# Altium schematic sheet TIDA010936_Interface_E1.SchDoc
size 431 x 279 mm; Date: Not shown in title block; ApprovedBy: Not shown in title block; CheckedBy: Not shown in title block; Author: Not shown in title block; CompanyName: Not shown in title block; Engineer: Not shown in title block; Organization: Not shown in title block; Address1: Not shown in title block; Address2: Not shown in title block; Address3: Not shown in title block; Address4: Not shown in title block; DocumentNumber: 2; Revision: Use project parameter SCH_Rev; SheetNumber: 3; SheetTotal: 5; PageSetup: Record=PageOptions¦CenterHorizontal=True¦CenterVertical=True¦PrintScale=1.00¦XCorrection=1.00¦YCorrection=1.00¦PrintKind=0¦BorderSize=5000000¦LeftOffset=0¦BottomOffset=0¦Orientation=2¦PaperLength=1000¦PaperWidth=1000¦Scale=100¦PaperSource=15¦PrintQuality=600¦MediaType=1¦DitherType=10¦PaperKind=Letter¦PrintScaleMode=1
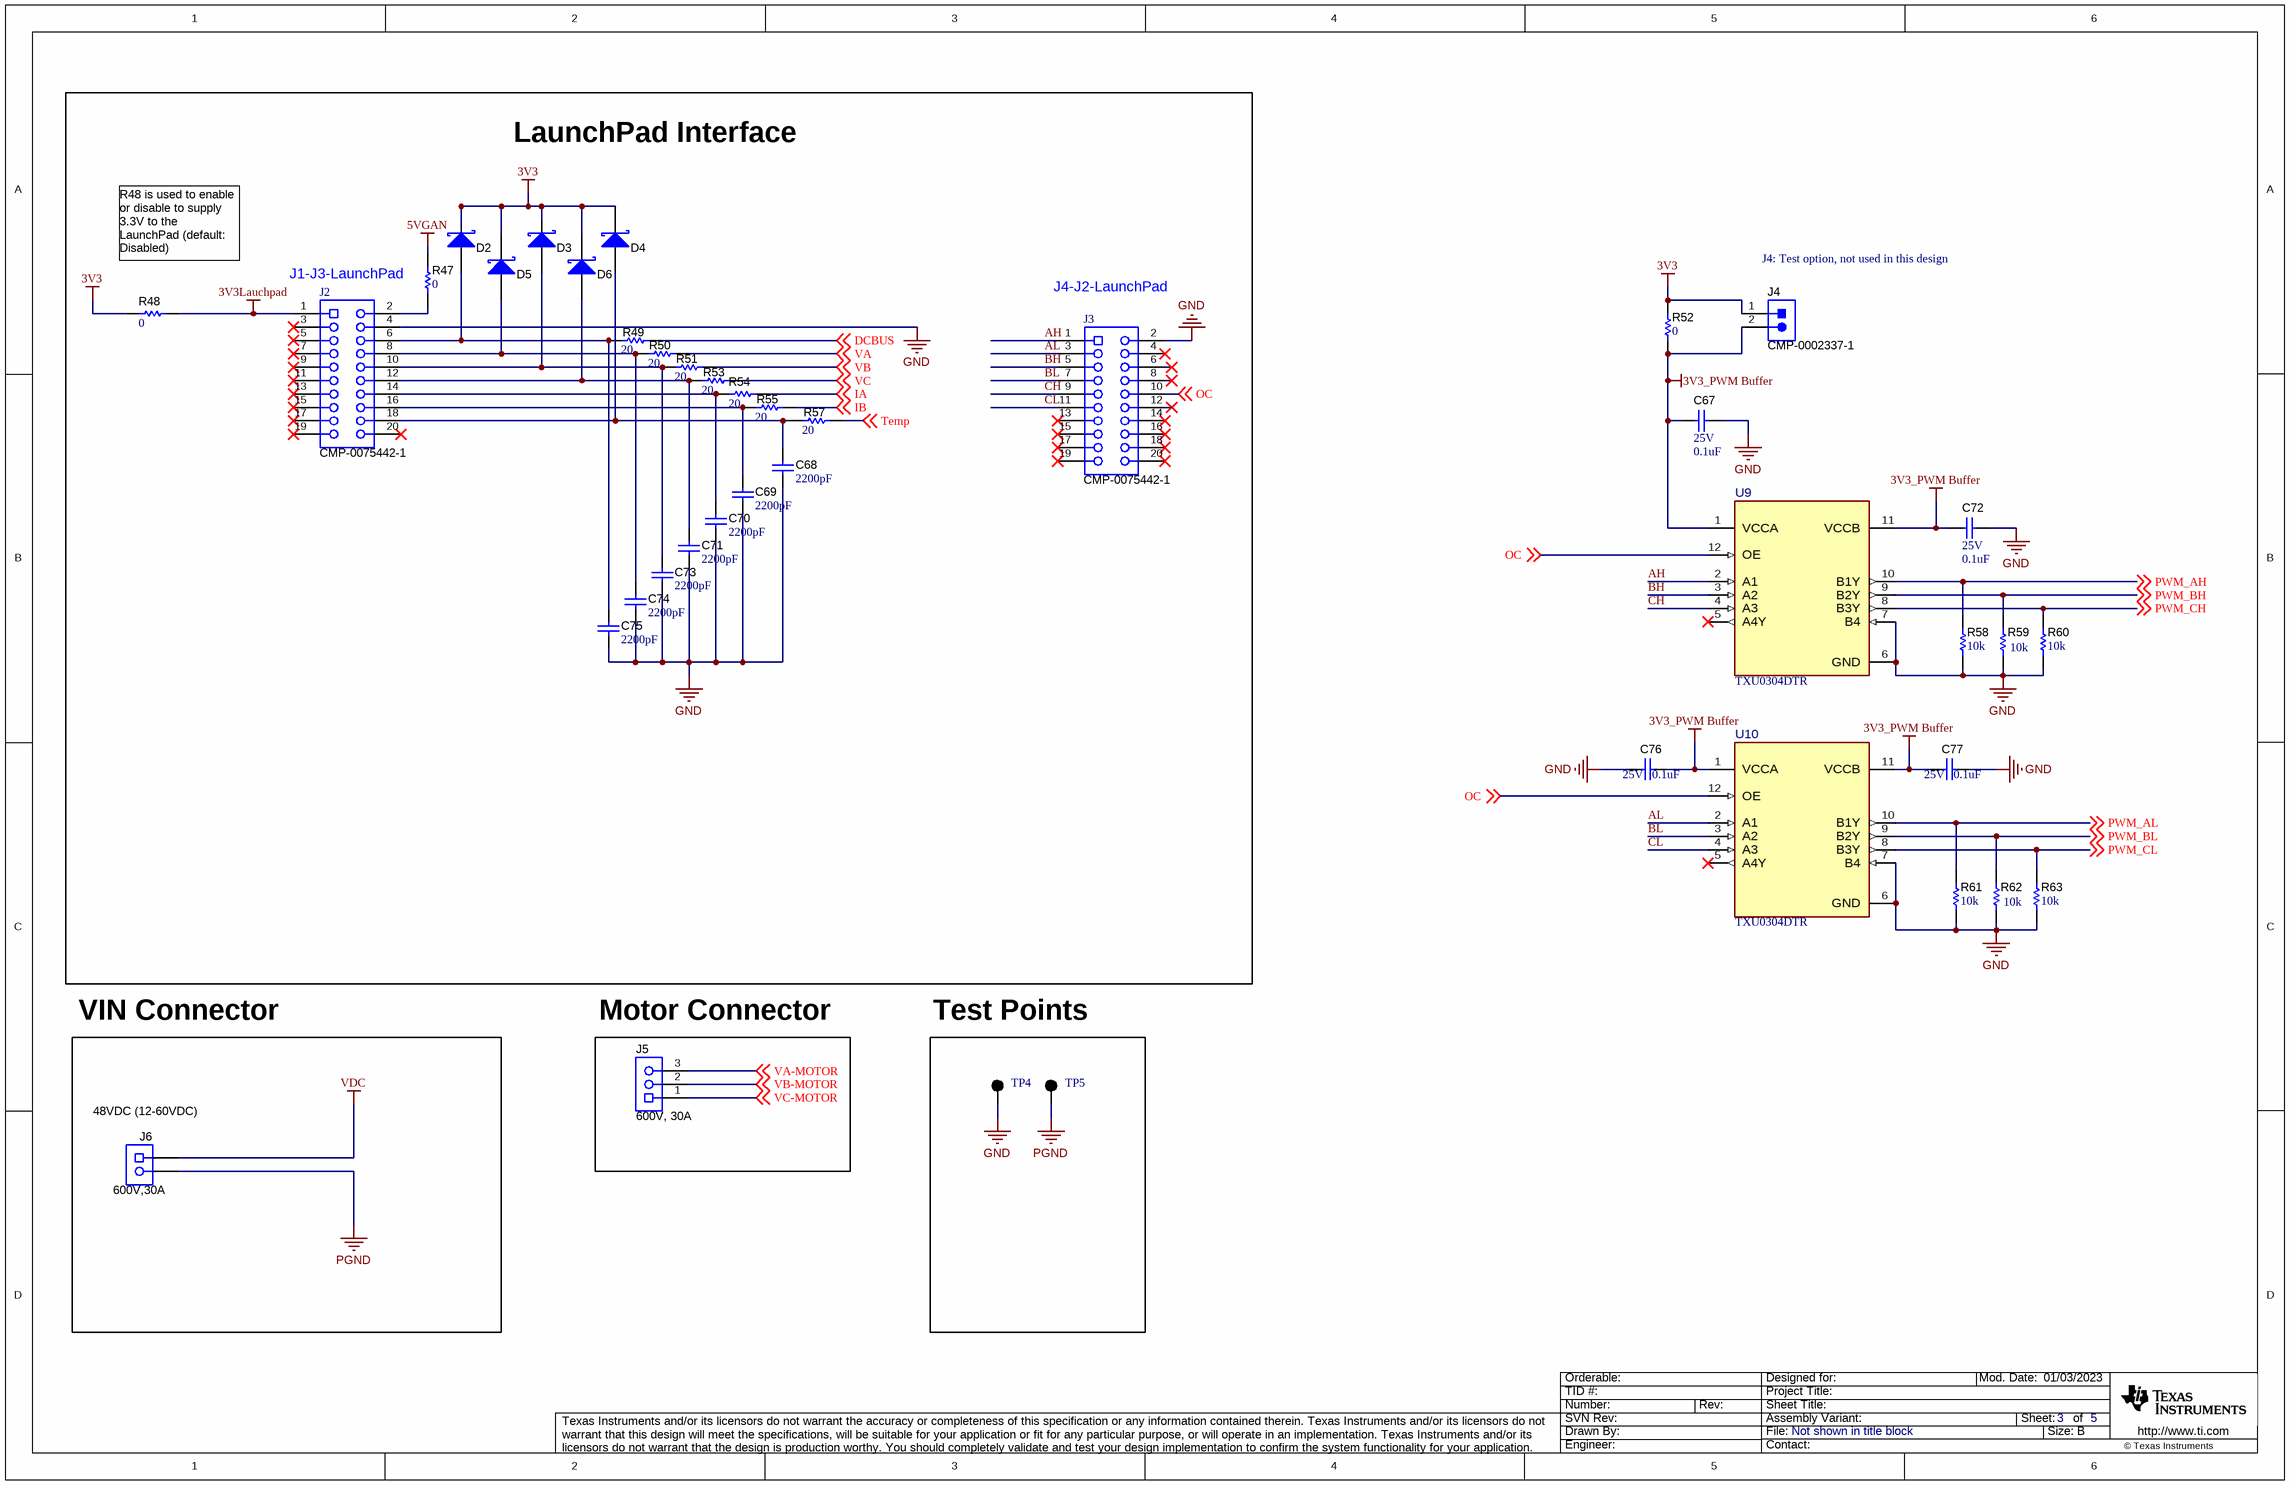
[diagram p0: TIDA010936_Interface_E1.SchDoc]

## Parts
C67  VDC_V: 25V  ValueDisplayed: 0.1uF  [0402]  (hidden comment: GRM155R71E104KE14D)
C68  ValueDisplayed: 2200pF  [0603]  (hidden comment: CMP-0006827-4)
C69  ValueDisplayed: 2200pF  [0603]  (hidden comment: CMP-0006827-4)
C70  ValueDisplayed: 2200pF  [0603]  (hidden comment: CMP-0006827-4)
C71  ValueDisplayed: 2200pF  [0603]  (hidden comment: CMP-0006827-4)
C72  VDC_V: 25V  ValueDisplayed: 0.1uF  [0402]  (hidden comment: GRM155R71E104KE14D)
C73  ValueDisplayed: 2200pF  [0603]  (hidden comment: CMP-0006827-4)
C74  ValueDisplayed: 2200pF  [0603]  (hidden comment: CMP-0006827-4)
C75  ValueDisplayed: 2200pF  [0603]  (hidden comment: CMP-0006827-4)
C76  VDC_V: 25V  ValueDisplayed: 0.1uF  [0402]  (hidden comment: GRM155R71E104KE14D)
C77  VDC_V: 25V  ValueDisplayed: 0.1uF  [0402]  (hidden comment: GRM155R71E104KE14D)
D2  CMP-0028644-3  [SOD-523]  (value not drawn)
D3  CMP-0028644-3  [SOD-523]  (value not drawn)
D4  CMP-0028644-3  [SOD-523]  (value not drawn)
D5  CMP-0028644-3  [SOD-523]  (value not drawn)
D6  CMP-0028644-3  [SOD-523]  (value not drawn)
J2  CMP-0075442-1  [CONN_SSW-110-23-F-D]
J3  CMP-0075442-1  [CONN_SSW-110-23-F-D]
J4  CMP-0002337-1  [CONN_PEC02SAAN]
J5  600V, 30A  [Phoenix_1904150]
J6  600V,30A  [Phoenix_1902547]
R47  ValueDisplayed: 0  [0603]  (hidden comment: PMR03EZPJ000)
R48  ValueDisplayed: 0  [0603]  (hidden comment: PMR03EZPJ000)
R49  ValueDisplayed: 20  [0402]  (hidden comment: CMP-0026876-3)
R50  ValueDisplayed: 20  [0402]  (hidden comment: CMP-0026876-3)
R51  ValueDisplayed: 20  [0402]  (hidden comment: CMP-0026876-3)
R52  ValueDisplayed: 0  [0402]  (hidden comment: CMP-0026822-3)
R53  ValueDisplayed: 20  [0402]  (hidden comment: CMP-0026876-3)
R54  ValueDisplayed: 20  [0402]  (hidden comment: CMP-0026876-3)
R55  ValueDisplayed: 20  [0402]  (hidden comment: CMP-0026876-3)
R57  ValueDisplayed: 20  [0402]  (hidden comment: CMP-0026876-3)
R58  ValueDisplayed: 10k  [0402]  (hidden comment: CMP-0026825-5)
R59  ValueDisplayed: 10k  [0402]  (hidden comment: CMP-0026825-5)
R60  ValueDisplayed: 10k  [0402]  (hidden comment: CMP-0026825-5)
R61  ValueDisplayed: 10k  [0402]  (hidden comment: CMP-0026825-5)
R62  ValueDisplayed: 10k  [0402]  (hidden comment: CMP-0026825-5)
R63  ValueDisplayed: 10k  [0402]  (hidden comment: CMP-0026825-5)
TP4  CMP-0055138-2  [Keystone5001]  (value not drawn)
TP5  CMP-0055138-2  [Keystone5001]  (value not drawn)
U9  TXU0304DTR  [DTR0012A-MFG]
U10  TXU0304DTR  [DTR0012A-MFG]

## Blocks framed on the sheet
LaunchPad Interface: C68-C71 C73-C75 D2-D6 J2 J3 R47-R51 R53-R55 R57
48VDC (12-60VDC): J6

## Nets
3V3: D2.1(K) D3.1(K) D4.1(K) D5.1(K) D6.1(K) J4.1 R48.2 R52.2
3V3_PWM Buffer: C67.1 C72.1 C76.2 C77.1 J4.2 R52.1 U9.1(VCCA) U9.11(VCCB) U10.1(VCCA) U10.11(VCCB)
3V3Lauchpad: J2.1 R48.1
5VGAN: R47.1
GND: C67.2 C68.2 C69.2 C70.2 C71.2 C72.2 C73.2 C74.2 C75.2 C76.1 C77.2 J2.4 J3.2 R58.1 R59.1 R60.1 R61.1 R62.1 R63.1 TP4.1 U9.6(GND) U9.7(B4) U10.6(GND) U10.7(B4)
PGND: J6.2 TP5.1
VDC: J6.1
AH: J3.1 U9.2(A1)
AL: J3.3 U10.2(A1)
BH: J3.5 U9.3(A2)
BL: J3.7 U10.3(A2)
CH: J3.9 U9.4(A3)
CL: J3.11 U10.4(A3)
DCBUS: R49.1 ; off-sheet DCBUS
IA: R54.1 ; off-sheet IA
IB: R55.1 ; off-sheet IB
OC: J3.10 U9.12(OE) U10.12(OE) ; off-sheet OC
PWM_AH: R58.2 U9.10(B1Y) ; off-sheet PWM_AH
PWM_AL: R61.2 U10.10(B1Y) ; off-sheet PWM_AL
PWM_BH: R59.2 U9.9(B2Y) ; off-sheet PWM_BH
PWM_BL: R62.2 U10.9(B2Y) ; off-sheet PWM_BL
PWM_CH: R60.2 U9.8(B3Y) ; off-sheet PWM_CH
PWM_CL: R63.2 U10.8(B3Y) ; off-sheet PWM_CL
Temp: R57.1 ; off-sheet Temp
VA: R50.1 ; off-sheet VA
VA-MOTOR: J5.3 ; off-sheet VA-MOTOR
VB: R51.1 ; off-sheet VB
VB-MOTOR: J5.2 ; off-sheet VB-MOTOR
VC: R53.1 ; off-sheet VC
VC-MOTOR: J5.1 ; off-sheet VC-MOTOR
NetC68_1: C68.1 D4.2(A) J2.18 R57.2
NetC69_1: C69.1 J2.16 R55.2
NetC70_1: C70.1 J2.14 R54.2
NetC71_1: C71.1 D6.2(A) J2.12 R53.2
NetC73_1: C73.1 D3.2(A) J2.10 R51.2
NetC74_1: C74.1 D5.2(A) J2.8 R50.2
NetC75_1: C75.1 D2.2(A) J2.6 R49.2
NetJ2_2: J2.2 R47.2

Not connected (* = marked no-connect by the designer): J2 3* 5* 7* 9* 11* 13* 15* 17* 19* 20*; J3 4* 6* 8* 12* 13* 14* 15* 16* 17* 18* 19* 20*; U9 5(A4Y)*; U10 5(A4Y)*

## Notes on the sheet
- R48 is used to enable or disable to supply 3.3V to the LaunchPad (default: Disabled)
- J1-J3-LaunchPad
- (near J3) J4-J2-LaunchPad
- (near J4) J4: Test option, not used in this design
- VIN Connector
- (near J5) Motor Connector
- Test Points

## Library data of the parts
C67 C72 C76 C77 = CMP-0006659-2: CAP, CERM, 0.1 uF, 25 V, +/- 10%, X7R, 0402; Manufacturer: MuRata; TaMin_C: -55°C; Polarized: N; SizeAreaWB_mm2: 3; Value1: Unknown; U/M: EA; Value: 0.1uF; TaMax_C: 125°C; SizeZ_mm: 0.6; SizeX_mm: 1; SizeY_mm: 0.5; Cap_F: 100nF; AEC Category: Q200
C68-C71 C73-C75 = CMP-0006827-4: CAP, CERM, 2200 pF, 16 V, +/- 10%, X7R, 0603; PartNumber: 885012206036; Manufacturer: Wurth Elektronik; Polarized: N; Value: 2200pF; U/M: EA; Cap_F: 2.2nF; Value1: Unknown; VDC_V: 16V; TaMin_C: -55°C; TaMax_C: 125°C; AEC Category: Q200; SizeArea_mm2: 1.28; SizeAreaWB_mm2: 4.68; SizeX_mm: 1.6; SizeY_mm: 0.8; SizeZ_mm: 1
D2-D6 = CMP-0028644-3: Diode, Schottky, 70 V, 0.07 A, SOD-523; PartNumber: 1PS79SB70,115; Manufacturer: Nexperia; Vf_V: 410mV; Value: 70V; Value1: 0.07A; Value2: 0.41V; Io_A: 70mA; TJmax_C: 150°C; SizeAreaWB_mm2: 5.13; SizeArea_mm2: 1.53; SizeX_mm: 1.7; SizeY_mm: 0.9; SizeZ_mm: 0.65; AEC Category: Q101; Green_Lifecycle: Not Set; Green_REACh: Incomplete
J2 J3 = CMP-0075442-1: Connector, Receptacle, 100mil, 10x2, Gold plated, TH; PartNumber: SSW-110-23-F-D; Manufacturer: Samtec; CompType: Socket Strip; Green_Lifecycle: Active; Green_REACh: Passed; CT: True; CNHeader: False
J4 = CMP-0002337-1: Header, 100mil, 2x1, Tin, TH; PartNumber: PEC02SAAN; Manufacturer: Sullins Connector Solutions; Pitch_mm: 2.54; Gender: Male; Shrouded: N; Row_Count: 1; Current_A: 3A; Voltage_V: 1.8kV; Cert_UL: Y; CNHeader: TRUE; Green_Lifecycle: Not Set; Green_REACh: Incomplete; CT: FALSE
J5 = CMP-0055528-1: Terminal Block, 9.52mm, 3x1, R/A, TH; Manufacturer: Phoenix Contact; PartNumber: 1904150; Cert_VDE: Y; CNHeader: FALSE; Current_A: 32A; Gender: Female; Voltage_V: 1kV; Row_Count: 1; Pitch_mm: 9.52; CT: TRUE
J6 = CMP-0055527-1: Terminal Block, 9.52mm, 2x1, R/A, TH; PartNumber: 1902547; Manufacturer: Phoenix Contact; Pitch_mm: 9.52; Gender: Female; Row_Count: 1; Current_A: 32A; Voltage_V: 1kV; Cert_UL: Y; CNHeader: FALSE; CT: TRUE
R47 R48 = CMP-0086358-1: RES, 0, 0%, 0.25 W, AEC-Q200 Grade 0, 0603; Manufacturer: Rohm; Power_W: 250mW; SizeZ_mm: 1; SizeArea_mm2: 1.28; Value2: 0.25W; SizeAreaWB_mm2: 4.68; Value_Code: 0000; Value: 0; AEC Qualified: Y; AEC Category: Q200; SizeX_mm: 1.6; SizeY_mm: 0.8
R49-R51 R53-R55 R57 = CMP-0026876-3: RES, 20, 5%, 0.063 W, AEC-Q200 Grade 0, 0402; PartNumber: CRCW040220R0JNED; Manufacturer: Vishay-Dale; Value: 20; Value_Code: 20R0; Power_W: 63mW; Value2: 0.063W; VDC_V: 50V; TempCo: 200 ppm/C; EIA_Code: E24; AEC Category: Q200; AEC Qualified: Y; AEC Grade: 0; SizeArea_mm2: 0.5; SizeX_mm: 1; SizeZ_mm: 0.6
R52 = CMP-0026822-3: RES, 0, 5%, 0.063 W, AEC-Q200 Grade 0, 0402; PartNumber: CRCW04020000Z0ED; Manufacturer: Vishay-Dale; Value: 0; Value_Code: 0000; Power_W: 63mW; Value2: 0.063W; VDC_V: 50V; TempCo: 200 ppm/C; SizeArea_mm2: 0.5; SizeX_mm: 1; SizeZ_mm: 0.6; EIA_Code: E24; AEC Category: Q200; AEC Qualified: Y
R58-R63 = CMP-0026825-5: RES, 10 k, 5%, 0.063 W, AEC-Q200 Grade 0, 0402; PartNumber: CRCW040210K0JNED; Manufacturer: Vishay-Dale; Value: 10k; Value_Code: 10k0; Power_W: 63mW; Value2: 0.063W; VDC_V: 50V; TempCo: 200 ppm/C; SizeArea_mm2: 0.5; SizeX_mm: 1; SizeZ_mm: 0.6; EIA_Code: E24; AEC Category: Q200; AEC Qualified: Y; AEC Grade: 0
TP4 TP5 = CMP-0055138-2: Test Point, Miniature, Black, TH; Manufacturer: Keystone Electronics; ContactFinish: Silver; CNHeader: FALSE; Green_Lifecycle: Active; Green_REACh: Passed; CT: TRUE
U9 U10 = CMP-0091905-2: 4-Bit Fixed Direction Voltage-Level Translator with SchmittTrigger Inputs, and Tri-State Outputs; Manufacturer: Texas Instruments; AEC Category: Q200; Number Of Outputs: 4; PositionCount: 1; V B Min: 1.1V; V A Max: 5.5V; CompType: IC; SizeZ_mm: 0.4mm; Standoff Height: 0mm; Logic Function Desc: Non-Inverting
